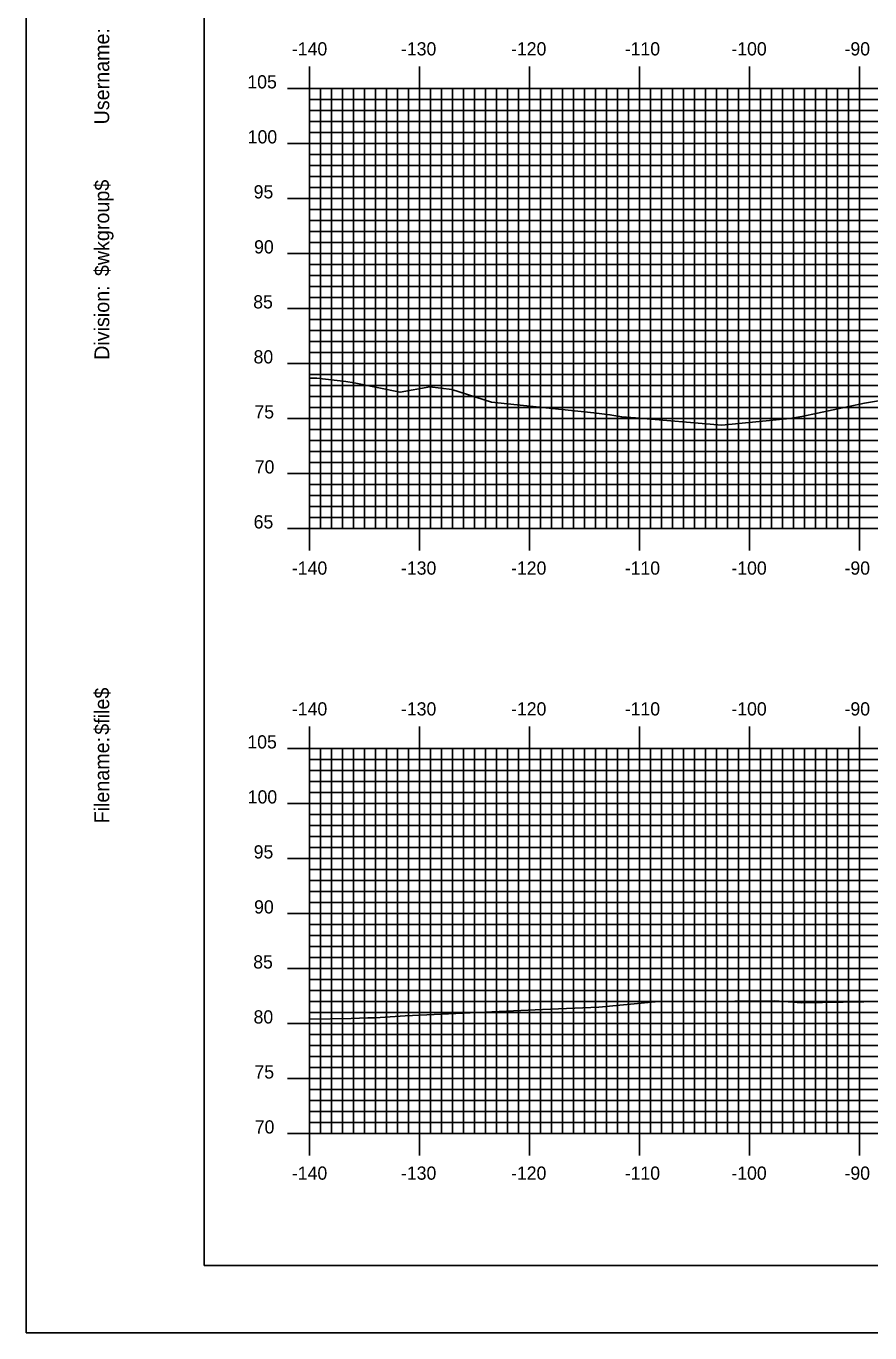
# Model space of a CAD drawing. Extents: x 852936 to 853279, y 364366 to 364586.
# Drawn here: x 852935.9 to 853012.6, y 364365.7 to 364484.5 of the extents above; entities that cross this region are included whole.
import ezdxf

# ---------------------------------------------------------------- set-up
doc = ezdxf.new("R2010")
doc.units = 0
for name, color, linetype in [('BORDER', 7, 'Continuous'), ('H_V ANNOTATION', 7, 'Continuous'), ('MAJOR', 7, 'Continuous'), ('MINOR', 7, 'Continuous'), ('PLOT BOUNDARY', 7, 'Continuous'), ('S_Roadway_Centerline', 7, 'Continuous')]:
    doc.layers.add(name, color=color, linetype=linetype)

msp = doc.modelspace()

# ---------------------------------------------------------------- linework, layer by layer
at = {"layer": 'BORDER'}
msp.add_lwpolyline([(852952.09, 364371.79), (853272.09, 364371.79), (853272.09, 364581.79), (852952.09, 364581.79)], close=True, dxfattribs=at)
at = {"layer": 'MAJOR'}
for p, q in [((852961.69, 364480.79), (852961.69, 364478.79)), ((852971.69, 364480.79), (852971.69, 364478.79)), ((852981.69, 364480.79), (852981.69, 364478.79)), ((852991.69, 364480.79), (852991.69, 364478.79)), ((853001.69, 364480.79), (853001.69, 364478.79)), ((853011.69, 364480.79), (853011.69, 364478.79)), ((852959.69, 364478.79), (852961.69, 364478.79)), ((852961.69, 364478.79), (853241.69, 364478.79)), ((852961.69, 364438.79), (852961.69, 364478.79)), ((852961.69, 364438.79), (852961.69, 364478.79)), ((852961.69, 364478.79), (853241.69, 364478.79)), ((852971.69, 364438.79), (852971.69, 364478.79)), ((852981.69, 364438.79), (852981.69, 364478.79)), ((852991.69, 364438.79), (852991.69, 364478.79)), ((853001.69, 364438.79), (853001.69, 364478.79)), ((853011.69, 364438.79), (853011.69, 364478.79)), ((852959.69, 364473.79), (852961.69, 364473.79)), ((852961.69, 364473.79), (853241.69, 364473.79)), ((852959.69, 364468.79), (852961.69, 364468.79)), ((852961.69, 364468.79), (853241.69, 364468.79)), ((852959.69, 364463.79), (852961.69, 364463.79)), ((852961.69, 364463.79), (853241.69, 364463.79)), ((852959.69, 364458.79), (852961.69, 364458.79)), ((852961.69, 364458.79), (853241.69, 364458.79)), ((852959.69, 364453.79), (852961.69, 364453.79)), ((852961.69, 364453.79), (853241.69, 364453.79)), ((852959.69, 364448.79), (852961.69, 364448.79)), ((852961.69, 364448.79), (853241.69, 364448.79)), ((852959.69, 364443.79), (852961.69, 364443.79)), ((852961.69, 364443.79), (853241.69, 364443.79)), ((852959.69, 364438.79), (852961.69, 364438.79)), ((852961.69, 364438.79), (853241.69, 364438.79)), ((852961.69, 364438.79), (853241.69, 364438.79)), ((852961.69, 364436.78), (852961.69, 364438.79)), ((852971.69, 364436.78), (852971.69, 364438.79)), ((852981.69, 364436.78), (852981.69, 364438.79)), ((852991.69, 364436.78), (852991.69, 364438.79)), ((853001.69, 364436.78), (853001.69, 364438.79)), ((853011.69, 364436.78), (853011.69, 364438.79)), ((852961.69, 364420.79), (852961.69, 364418.79)), ((852971.69, 364420.79), (852971.69, 364418.79)), ((852981.69, 364420.79), (852981.69, 364418.79)), ((852991.69, 364420.79), (852991.69, 364418.79)), ((853001.69, 364420.79), (853001.69, 364418.79)), ((853011.69, 364420.79), (853011.69, 364418.79)), ((852959.69, 364418.79), (852961.69, 364418.79)), ((852961.69, 364418.79), (853241.69, 364418.79)), ((852961.69, 364383.79), (852961.69, 364418.79)), ((852961.69, 364383.79), (852961.69, 364418.79)), ((852961.69, 364418.79), (853241.69, 364418.79)), ((852971.69, 364383.79), (852971.69, 364418.79)), ((852981.69, 364383.79), (852981.69, 364418.79)), ((852991.69, 364383.79), (852991.69, 364418.79)), ((853001.69, 364383.79), (853001.69, 364418.79)), ((853011.69, 364383.79), (853011.69, 364418.79)), ((852959.69, 364413.79), (852961.69, 364413.79)), ((852961.69, 364413.79), (853241.69, 364413.79)), ((852959.69, 364408.79), (852961.69, 364408.79)), ((852961.69, 364408.79), (853241.69, 364408.79)), ((852959.69, 364403.79), (852961.69, 364403.79)), ((852961.69, 364403.79), (853241.69, 364403.79)), ((852959.69, 364398.79), (852961.69, 364398.79)), ((852961.69, 364398.79), (853241.69, 364398.79)), ((852959.69, 364393.79), (852961.69, 364393.79)), ((852961.69, 364393.79), (853241.69, 364393.79)), ((852959.69, 364388.79), (852961.69, 364388.79)), ((852961.69, 364388.79), (853241.69, 364388.79)), ((852959.69, 364383.79), (852961.69, 364383.79)), ((852961.69, 364383.79), (853241.69, 364383.79)), ((852961.69, 364383.79), (853241.69, 364383.79)), ((852961.69, 364381.78), (852961.69, 364383.79)), ((852971.69, 364381.78), (852971.69, 364383.79)), ((852981.69, 364381.78), (852981.69, 364383.79)), ((852991.69, 364381.78), (852991.69, 364383.79)), ((853001.69, 364381.78), (853001.69, 364383.79)), ((853011.69, 364381.78), (853011.69, 364383.79))]:
    msp.add_line(p, q, dxfattribs=at)
at = {"layer": 'MINOR'}
for p, q in [((852962.69, 364438.79), (852962.69, 364478.79)), ((852963.69, 364438.79), (852963.69, 364478.79)), ((852964.69, 364438.79), (852964.69, 364478.79)), ((852965.69, 364438.79), (852965.69, 364478.79)), ((852966.69, 364438.79), (852966.69, 364478.79)), ((852967.69, 364438.79), (852967.69, 364478.79)), ((852968.69, 364438.79), (852968.69, 364478.79)), ((852969.69, 364438.79), (852969.69, 364478.79)), ((852970.69, 364438.79), (852970.69, 364478.79)), ((852972.69, 364438.79), (852972.69, 364478.79)), ((852973.69, 364438.79), (852973.69, 364478.79)), ((852974.69, 364438.79), (852974.69, 364478.79)), ((852975.69, 364438.79), (852975.69, 364478.79)), ((852976.69, 364438.79), (852976.69, 364478.79)), ((852977.69, 364438.79), (852977.69, 364478.79)), ((852978.69, 364438.79), (852978.69, 364478.79)), ((852979.69, 364438.79), (852979.69, 364478.79)), ((852980.69, 364438.79), (852980.69, 364478.79)), ((852982.69, 364438.79), (852982.69, 364478.79)), ((852983.69, 364438.79), (852983.69, 364478.79)), ((852984.69, 364438.79), (852984.69, 364478.79)), ((852985.69, 364438.79), (852985.69, 364478.79)), ((852986.69, 364438.79), (852986.69, 364478.79)), ((852987.69, 364438.79), (852987.69, 364478.79)), ((852988.69, 364438.79), (852988.69, 364478.79)), ((852989.69, 364438.79), (852989.69, 364478.79)), ((852990.69, 364438.79), (852990.69, 364478.79)), ((852992.69, 364438.79), (852992.69, 364478.79)), ((852993.69, 364438.79), (852993.69, 364478.79)), ((852994.69, 364438.79), (852994.69, 364478.79)), ((852995.69, 364438.79), (852995.69, 364478.79)), ((852996.69, 364438.79), (852996.69, 364478.79)), ((852997.69, 364438.79), (852997.69, 364478.79)), ((852998.69, 364438.79), (852998.69, 364478.79)), ((852999.69, 364438.79), (852999.69, 364478.79)), ((853000.69, 364438.79), (853000.69, 364478.79)), ((853002.69, 364438.79), (853002.69, 364478.79)), ((853003.69, 364438.79), (853003.69, 364478.79)), ((853004.69, 364438.79), (853004.69, 364478.79)), ((853005.69, 364438.79), (853005.69, 364478.79)), ((853006.69, 364438.79), (853006.69, 364478.79)), ((853007.69, 364438.79), (853007.69, 364478.79)), ((853008.69, 364438.79), (853008.69, 364478.79)), ((853009.69, 364438.79), (853009.69, 364478.79)), ((853010.69, 364438.79), (853010.69, 364478.79)), ((852961.69, 364477.79), (853241.69, 364477.79)), ((852961.69, 364477.79), (852963.7, 364477.79)), ((852961.69, 364476.79), (853241.69, 364476.79)), ((852961.69, 364476.79), (852963.7, 364476.79)), ((852961.69, 364475.79), (853241.69, 364475.79)), ((852961.69, 364475.79), (852963.7, 364475.79)), ((852961.69, 364474.79), (853241.69, 364474.79)), ((852961.69, 364474.79), (852963.7, 364474.79)), ((852961.69, 364472.79), (853241.69, 364472.79)), ((852961.69, 364472.79), (852963.7, 364472.79)), ((852961.69, 364471.79), (853241.69, 364471.79)), ((852961.69, 364471.79), (852963.7, 364471.79)), ((852961.69, 364470.79), (853241.69, 364470.79)), ((852961.69, 364470.79), (852963.7, 364470.79)), ((852961.69, 364469.79), (853241.69, 364469.79)), ((852961.69, 364469.79), (852963.7, 364469.79)), ((852961.69, 364467.79), (853241.69, 364467.79)), ((852961.69, 364467.79), (852963.7, 364467.79)), ((852961.69, 364466.79), (853241.69, 364466.79)), ((852961.69, 364466.79), (852963.7, 364466.79)), ((852961.69, 364465.79), (853241.69, 364465.79)), ((852961.69, 364465.79), (852963.7, 364465.79)), ((852961.69, 364464.79), (853241.69, 364464.79)), ((852961.69, 364464.79), (852963.7, 364464.79)), ((852961.69, 364462.79), (853241.69, 364462.79)), ((852961.69, 364462.79), (852963.7, 364462.79)), ((852961.69, 364461.79), (853241.69, 364461.79)), ((852961.69, 364461.79), (852963.7, 364461.79)), ((852961.69, 364460.79), (853241.69, 364460.79)), ((852961.69, 364460.79), (852963.7, 364460.79)), ((852961.69, 364459.79), (853241.69, 364459.79)), ((852961.69, 364459.79), (852963.7, 364459.79)), ((852961.69, 364457.79), (853241.69, 364457.79)), ((852961.69, 364457.79), (852963.7, 364457.79)), ((852961.69, 364456.79), (853241.69, 364456.79)), ((852961.69, 364456.79), (852963.7, 364456.79)), ((852961.69, 364455.79), (853241.69, 364455.79)), ((852961.69, 364455.79), (852963.7, 364455.79)), ((852961.69, 364454.79), (853241.69, 364454.79)), ((852961.69, 364454.79), (852963.7, 364454.79)), ((852961.69, 364452.79), (853241.69, 364452.79)), ((852961.69, 364452.79), (852963.7, 364452.79)), ((852961.69, 364451.79), (853241.69, 364451.79)), ((852961.69, 364451.79), (852963.7, 364451.79)), ((852961.69, 364450.79), (853241.69, 364450.79)), ((852961.69, 364450.79), (852963.7, 364450.79)), ((852961.69, 364449.79), (853241.69, 364449.79)), ((852961.69, 364449.79), (852963.7, 364449.79)), ((852961.69, 364447.79), (853241.69, 364447.79)), ((852961.69, 364447.79), (852963.7, 364447.79)), ((852961.69, 364446.79), (853241.69, 364446.79)), ((852961.69, 364446.79), (852963.7, 364446.79)), ((852961.69, 364445.79), (853241.69, 364445.79)), ((852961.69, 364445.79), (852963.7, 364445.79)), ((852961.69, 364444.79), (853241.69, 364444.79)), ((852961.69, 364444.79), (852963.7, 364444.79)), ((852961.69, 364442.79), (853241.69, 364442.79)), ((852961.69, 364442.79), (852963.7, 364442.79)), ((852961.69, 364441.79), (853241.69, 364441.79)), ((852961.69, 364441.79), (852963.7, 364441.79)), ((852961.69, 364440.79), (853241.69, 364440.79)), ((852961.69, 364440.79), (852963.7, 364440.79)), ((852961.69, 364439.79), (853241.69, 364439.79)), ((852961.69, 364439.79), (852963.7, 364439.79)), ((852961.69, 364417.79), (853241.69, 364417.79)), ((852961.69, 364417.79), (852963.7, 364417.79)), ((852962.69, 364383.79), (852962.69, 364418.79)), ((852963.69, 364383.79), (852963.69, 364418.79)), ((852964.69, 364383.79), (852964.69, 364418.79)), ((852965.69, 364383.79), (852965.69, 364418.79)), ((852966.69, 364383.79), (852966.69, 364418.79)), ((852967.69, 364383.79), (852967.69, 364418.79)), ((852968.69, 364383.79), (852968.69, 364418.79)), ((852969.69, 364383.79), (852969.69, 364418.79)), ((852970.69, 364383.79), (852970.69, 364418.79)), ((852972.69, 364383.79), (852972.69, 364418.79)), ((852973.69, 364383.79), (852973.69, 364418.79)), ((852974.69, 364383.79), (852974.69, 364418.79)), ((852975.69, 364383.79), (852975.69, 364418.79)), ((852976.69, 364383.79), (852976.69, 364418.79)), ((852977.69, 364383.79), (852977.69, 364418.79)), ((852978.69, 364383.79), (852978.69, 364418.79)), ((852979.69, 364383.79), (852979.69, 364418.79)), ((852980.69, 364383.79), (852980.69, 364418.79)), ((852982.69, 364383.79), (852982.69, 364418.79)), ((852983.69, 364383.79), (852983.69, 364418.79)), ((852984.69, 364383.79), (852984.69, 364418.79)), ((852985.69, 364383.79), (852985.69, 364418.79)), ((852986.69, 364383.79), (852986.69, 364418.79)), ((852987.69, 364383.79), (852987.69, 364418.79)), ((852988.69, 364383.79), (852988.69, 364418.79)), ((852989.69, 364383.79), (852989.69, 364418.79)), ((852990.69, 364383.79), (852990.69, 364418.79)), ((852992.69, 364383.79), (852992.69, 364418.79)), ((852993.69, 364383.79), (852993.69, 364418.79)), ((852994.69, 364383.79), (852994.69, 364418.79)), ((852995.69, 364383.79), (852995.69, 364418.79)), ((852996.69, 364383.79), (852996.69, 364418.79)), ((852997.69, 364383.79), (852997.69, 364418.79)), ((852998.69, 364383.79), (852998.69, 364418.79)), ((852999.69, 364383.79), (852999.69, 364418.79)), ((853000.69, 364383.79), (853000.69, 364418.79)), ((853002.69, 364383.79), (853002.69, 364418.79)), ((853003.69, 364383.79), (853003.69, 364418.79)), ((853004.69, 364383.79), (853004.69, 364418.79)), ((853005.69, 364383.79), (853005.69, 364418.79)), ((853006.69, 364383.79), (853006.69, 364418.79)), ((853007.69, 364383.79), (853007.69, 364418.79)), ((853008.69, 364383.79), (853008.69, 364418.79)), ((853009.69, 364383.79), (853009.69, 364418.79)), ((853010.69, 364383.79), (853010.69, 364418.79)), ((852961.69, 364416.79), (853241.69, 364416.79)), ((852961.69, 364416.79), (852963.7, 364416.79)), ((852961.69, 364415.79), (853241.69, 364415.79)), ((852961.69, 364415.79), (852963.7, 364415.79)), ((852961.69, 364414.79), (853241.69, 364414.79)), ((852961.69, 364414.79), (852963.7, 364414.79)), ((852961.69, 364412.79), (853241.69, 364412.79)), ((852961.69, 364412.79), (852963.7, 364412.79)), ((852961.69, 364411.79), (853241.69, 364411.79)), ((852961.69, 364411.79), (852963.7, 364411.79)), ((852961.69, 364410.79), (853241.69, 364410.79)), ((852961.69, 364410.79), (852963.7, 364410.79)), ((852961.69, 364409.79), (853241.69, 364409.79)), ((852961.69, 364409.79), (852963.7, 364409.79)), ((852961.69, 364407.79), (853241.69, 364407.79)), ((852961.69, 364407.79), (852963.7, 364407.79)), ((852961.69, 364406.79), (853241.69, 364406.79)), ((852961.69, 364406.79), (852963.7, 364406.79)), ((852961.69, 364405.79), (853241.69, 364405.79)), ((852961.69, 364405.79), (852963.7, 364405.79)), ((852961.69, 364404.79), (853241.69, 364404.79)), ((852961.69, 364404.79), (852963.7, 364404.79)), ((852961.69, 364402.79), (853241.69, 364402.79)), ((852961.69, 364402.79), (852963.7, 364402.79)), ((852961.69, 364401.79), (853241.69, 364401.79)), ((852961.69, 364401.79), (852963.7, 364401.79)), ((852961.69, 364400.79), (853241.69, 364400.79)), ((852961.69, 364400.79), (852963.7, 364400.79)), ((852961.69, 364399.79), (853241.69, 364399.79)), ((852961.69, 364399.79), (852963.7, 364399.79)), ((852961.69, 364397.79), (853241.69, 364397.79)), ((852961.69, 364397.79), (852963.7, 364397.79)), ((852961.69, 364396.79), (853241.69, 364396.79)), ((852961.69, 364396.79), (852963.7, 364396.79)), ((852961.69, 364395.79), (853241.69, 364395.79)), ((852961.69, 364395.79), (852963.7, 364395.79)), ((852961.69, 364394.79), (853241.69, 364394.79)), ((852961.69, 364394.79), (852963.7, 364394.79)), ((852961.69, 364392.79), (853241.69, 364392.79)), ((852961.69, 364392.79), (852963.7, 364392.79)), ((852961.69, 364391.79), (853241.69, 364391.79)), ((852961.69, 364391.79), (852963.7, 364391.79)), ((852961.69, 364390.79), (853241.69, 364390.79)), ((852961.69, 364390.79), (852963.7, 364390.79)), ((852961.69, 364389.79), (853241.69, 364389.79)), ((852961.69, 364389.79), (852963.7, 364389.79)), ((852961.69, 364387.79), (853241.69, 364387.79)), ((852961.69, 364387.79), (852963.7, 364387.79)), ((852961.69, 364386.79), (853241.69, 364386.79)), ((852961.69, 364386.79), (852963.7, 364386.79)), ((852961.69, 364385.79), (853241.69, 364385.79)), ((852961.69, 364385.79), (852963.7, 364385.79)), ((852961.69, 364384.79), (853241.69, 364384.79)), ((852961.69, 364384.79), (852963.7, 364384.79))]:
    msp.add_line(p, q, dxfattribs=at)
at = {"layer": 'PLOT BOUNDARY'}
msp.add_lwpolyline([(852935.9, 364365.67), (853275.9, 364365.67), (853275.9, 364585.67), (852935.9, 364585.67)], close=True, dxfattribs=at)
at = {"layer": 'S_Roadway_Centerline'}
for points in [[(852961.69, 364452.45), (852962.35, 364452.45), (852964.97, 364452.16), (852965.73, 364452.04), (852969.92, 364451.17), (852972.61, 364451.65), (852974.62, 364451.42), (852978.23, 364450.28), (852987.55, 364449.29), (852989, 364449.12), (852990.08, 364448.93), (852991.34, 364448.84), (852999.19, 364448.18), (853005.36, 364448.79), (853006.46, 364448.98), (853012.17, 364450.18), (853016.32, 364450.88)], [(852961.69, 364394.18), (852965.46, 364394.24), (852966.99, 364394.32), (852967.65, 364394.31), (852970.38, 364394.49), (852982.86, 364395.05), (852988, 364395.28), (852993.13, 364395.77), (853003.97, 364395.86), (853006.46, 364395.67), (853015.84, 364395.83), (853020.86, 364395.43), (853022.84, 364395.52), (853029.16, 364395.65), (853041.36, 364395.71), (853045.19, 364395.8), (853054.1, 364395.63), (853059.55, 364395.51), (853065.7, 364395.52), (853077.73, 364395.63), (853081.31, 364395.49), (853092.62, 364395.78)]]:
    msp.add_lwpolyline(points, dxfattribs=at)

# ---------------------------------------------------------------- texts
at = {"layer": 'BORDER'}
for s, p in [('Username:', (852943.46, 364475.52)), ('$wkgroup$', (852943.46, 364461.73)), ('Division:', (852943.46, 364454.12)), ('$file$', (852943.46, 364420.04)), ('Filename:', (852943.46, 364411.98))]:
    msp.add_text(s, height=1.339, rotation=90, dxfattribs=at).set_placement(p)
at = {"layer": 'H_V ANNOTATION'}
for s, p in [('-140', (852960.08, 364481.79)), ('-130', (852970, 364481.79)), ('-120', (852980.01, 364481.79)), ('-110', (852990.35, 364481.79)), ('-100', (853000.05, 364481.79)), ('-90', (853010.34, 364481.79)), ('105', (852956.03, 364478.79)), ('100', (852956.06, 364473.79)), ('95', (852956.6, 364468.79)), ('90', (852956.64, 364463.79)), ('85', (852956.56, 364458.79)), ('80', (852956.59, 364453.79)), ('75', (852956.67, 364448.79)), ('70', (852956.7, 364443.79)), ('65', (852956.6, 364438.79)), ('-140', (852960.08, 364434.59)), ('-130', (852970, 364434.59)), ('-120', (852980.01, 364434.59)), ('-110', (852990.35, 364434.59)), ('-100', (853000.05, 364434.59)), ('-90', (853010.34, 364434.59)), ('-140', (852960.08, 364421.79)), ('-130', (852970, 364421.79)), ('-120', (852980.01, 364421.79)), ('-110', (852990.35, 364421.79)), ('-100', (853000.05, 364421.79)), ('-90', (853010.34, 364421.79)), ('105', (852956.03, 364418.79)), ('100', (852956.06, 364413.79)), ('95', (852956.6, 364408.79)), ('90', (852956.64, 364403.79)), ('85', (852956.56, 364398.79)), ('80', (852956.59, 364393.79)), ('75', (852956.67, 364388.79)), ('70', (852956.7, 364383.79)), ('-140', (852960.08, 364379.59)), ('-130', (852970, 364379.59)), ('-120', (852980.01, 364379.59)), ('-110', (852990.35, 364379.59)), ('-100', (853000.05, 364379.59)), ('-90', (853010.34, 364379.59))]:
    msp.add_text(s, height=1.2, dxfattribs=at).set_placement(p)
at = {"layer": 'MAJOR'}
for p in [(852961.68, 364438.79), (852961.68, 364383.79)]:
    msp.add_text('-', height=0.012, dxfattribs=at).set_placement(p)

doc.saveas('drawing.dxf')
